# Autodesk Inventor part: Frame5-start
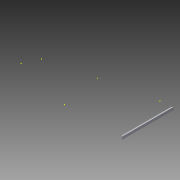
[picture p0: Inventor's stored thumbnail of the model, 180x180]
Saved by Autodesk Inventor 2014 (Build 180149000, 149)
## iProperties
Created: 2009-05
Part Number: Frame5-start
Document SubType Name: Modeling
Designer: millerpa
Density: 1 g/cm^3
Material: Generic
Appearance: Default
Author: millerpa
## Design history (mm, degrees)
derived "Skeleton-frame-start.ipt"
  sketch "Sketch6"
    geometry: L1 (-19.05, -44.45)-(19.05, -44.45) reference; L2 (19.05, -44.45)-(19.05, 44.45) reference; L3 (19.05, 44.45)-(-19.05, 44.45) reference; L4 (-19.05, 44.45)-(-19.05, -44.45) reference; 4 further points
  workplane "Work Plane1"
  workplane "Work Plane2"
  workplane "Work Plane3"
  workplane "Work Plane4"
  workplane "Work Plane5"
  workplane "Work Plane6"
extrude "Extrusion1" new body sketch "Sketch6" stored distance "d4" = 10; taper "d6" = 0 deg
body "Solid1"
feature "Srf4::Skeleton-frame-start.ipt"
body "Srf1"
feature "Srf5::Skeleton-frame-start.ipt"
body "Srf2"
other parameters: "d52" = 45 deg, "d53" = 45 deg, "d0_1" = 3772.27615, "d1" = 914.4, "d2" = 1662.8558, "d26" = 38.1, "d27" = 88.9, "d28" = 19.05, "d29" = 44.45, "d30" = 76.2, "d31" = 127, "d32" = 38.1, "d33" = 88.9, "d34" = 19.05, "d35" = 44.45, "d36" = 76.2, "d37" = 127, "d38" = 38.1, "d39" = 88.9, "d40" = 19.05, "d41" = 44.45, "d42" = 76.2, "d43" = 127, "d44" = 38.1, "d45" = 88.9, "d46" = 19.05, "d47" = 44.45, "d48" = 76.2, "d49" = 127, "d3" = 14.25776, "d5" = 14.25776, "d7" = 14.25776, "d8" = 14.25776, "d9" = 304.8, "d10" = 304.8, "FrameW" = 38.1, "FrameH" = 88.9, "d12" = 38.1, "d13" = 88.9, "d14" = 19.05, "d15" = 44.45, "d16" = 38.1, "d17" = 88.9, "d18" = 19.05, "d19" = 44.45, "d20" = 76.2, "d21" = 127
